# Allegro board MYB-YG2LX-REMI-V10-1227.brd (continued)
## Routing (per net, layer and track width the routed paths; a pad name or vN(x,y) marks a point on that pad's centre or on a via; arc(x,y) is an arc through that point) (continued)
RZ_DSI_DATA2_N: length 58.9
  TOP w0.13: v1(29.28,26.71) 29.11,26.54 28.78,26.54 R97.2 ; v1(60.21,52.94) 60.37,53.1 60.37,54.44 60.69,54.75 60.69,55.09 60.35,55.43 U26.69
  ART03 w0.109: v1(60.21,52.94) 60.37,52.77 60.37,52.56 60.26,52.45 59.76,52.45 59.63,52.58 59.63,52.76 59.49,52.91 59.31,52.91 59.16,53.05 59.16,53.23 59.02,53.37 58.84,53.37 58.7,53.51 58.7,53.69 58.56,53.83 58.38,53.83 58.11,54.1 56.54,54.1 56.13,54.51 50.75,54.51 50.36,54.89 45.56,54.89 44.82,54.15 43.47,54.15 42.76,53.44 41.19,53.44 40.71,52.96 40.71,48.47 32.41,40.16 32.41,38.51 31.09,37.19 31.09,27.31 30.84,27.07 30.67,27.07 30.52,26.92 30.52,26.75 30.32,26.54 30.14,26.54 30.01,26.67 29.82,26.67 29.69,26.54 29.44,26.54 v1(29.28,26.71)
RZ_DSI_DATA2_P: length 58.9
  TOP w0.13: R96.2 28.78,26.21 29.11,26.21 v1(29.28,26.05) ; U26.68 61.35,55.43 61.01,55.09 61.01,54.62 60.7,54.3 60.7,53.1 v1(60.87,52.94)
  ART03 w0.109: v1(29.28,26.05) 29.44,26.21 30.45,26.21 31.41,27.18 31.41,37.05 32.73,38.37 32.73,40.03 41.04,48.34 41.04,52.83 41.33,53.11 42.9,53.11 43.61,53.83 44.96,53.83 45.69,54.56 50.23,54.56 50.61,54.18 55.99,54.18 56.4,53.77 57.98,53.77 59.63,52.12 60.4,52.12 60.7,52.42 60.7,52.77 v1(60.87,52.94)
RZ_DSI_DATA3_N: length 57.7
  TOP w0.13: v1(29.28,28.49) 29.11,28.32 28.78,28.32 R99.2 ; U26.78 51.68,55.84 51.68,55.49 v1(51.52,55.32)
  ART03 w0.109: v1(51.52,55.32) 51.39,55.19 51.1,55.19 50.94,55.36 50.94,55.49 51.17,55.73 51.17,55.86 51.07,55.96 50.94,55.96 50.7,55.73 50.57,55.73 50.08,56.21 45.03,56.21 44.73,55.91 44.73,55.48 44.62,55.37 44.18,55.37 44.07,55.48 44.07,55.91 43.77,56.21 42.26,56.21 39.61,53.57 38.96,53.57 38.58,53.19 38.58,52.39 38.88,52.09 39.77,52.09 39.88,51.98 39.88,51.54 39.77,51.43 38.88,51.43 38.58,51.13 38.58,50.42 38.88,50.12 39.77,50.12 39.88,50.01 39.88,49.58 39.77,49.47 37.88,49.47 37.51,49.1 37.51,48.34 37.41,48.23 36.54,48.23 36.24,47.93 36.24,47.22 36.54,46.92 37.38,46.92 37.49,46.81 37.49,46.62 36.84,45.97 35.78,45.97 35.25,45.44 35.25,44.64 35.07,44.45 33.52,44.45 33.19,44.12 33.19,43.49 32.98,43.28 31.72,43.28 31.24,42.8 31.24,42.08 32.03,41.29 32.03,41.07 31.52,40.56 31.52,38.82 30.25,37.55 30.25,28.53 30.04,28.32 29.44,28.32 v1(29.28,28.49)
RZ_DSI_DATA3_P: length 57.8
  TOP w0.13: v1(29.28,27.83) 29.11,27.99 28.78,27.99 R98.2 ; v1(52.18,55.32) 52.01,55.49 52.01,55.84 U26.77
  ART03 w0.109: v1(29.28,27.83) 29.44,27.99 30.17,27.99 30.58,28.4 30.58,37.41 31.85,38.68 31.85,40.43 32.36,40.94 32.36,41.43 31.57,42.22 31.57,42.66 31.86,42.95 33.12,42.95 33.52,43.36 33.52,43.98 33.66,44.12 35.2,44.12 35.58,44.5 35.58,45.31 35.92,45.64 36.98,45.64 37.82,46.48 37.82,46.95 37.52,47.25 36.68,47.25 36.57,47.36 36.57,47.8 36.68,47.9 37.54,47.9 37.84,48.21 37.84,48.96 38.02,49.14 39.9,49.14 40.2,49.44 40.2,50.15 39.9,50.45 39.02,50.45 38.91,50.56 38.91,51 39.02,51.11 39.9,51.11 40.2,51.41 40.2,52.12 39.9,52.42 39.02,52.42 38.91,52.53 38.91,53.05 39.1,53.24 39.75,53.24 42.39,55.88 43.64,55.88 43.74,55.77 43.74,55.34 44.05,55.04 44.75,55.04 45.06,55.34 45.06,55.77 45.16,55.88 49.95,55.88 50.97,54.87 51.86,54.87 52.06,55.07 52.06,55.2 v1(52.18,55.32)
RZ_MD_BOOT0: length 20.3
  TOP w0.152: U26.156 78.36,11.17 78.36,10.82 79.52,9.65 88.79,9.65 90.95,7.49 90.95,3.61 91.59,2.97 SW1.8
RZ_MD_BOOT1: length 22.2
  TOP w0.152: v1(91.46,4.25) SW1.7 93.4,4.25 94.03,4.88 94.03,7.16 93.65,7.54 92.54,7.54 91.35,8.74 90.62,8.74 88.97,10.39 80.94,10.39 80.35,10.99 U26.158
  BOTTOM w0.152: R64.1 92.38,4.4 92.22,4.25 v1(91.46,4.25)
RZ_MD_BOOT2: length 18.2
  TOP w0.152: SW1.6 91.69,5.51 91.46,5.74 v1(91.46,6.3) 91.46,7.47 88.97,9.96 79.7,9.96 79.35,10.31 U26.157
  BOTTOM w0.152: v1(91.46,6.3) 91.49,6.32 R65.1
RZ_P1_0_USER_KEY: length 131.6
  TOP w0.152: v1(46.4,42.19) 46.81,41.78 46.81,37.52 46.47,37.18 U26.100 ; v1(112.95,5.69) 113.51,5.13 S2.4 S2.3
  ART03 w0.152: v1(104.03,6.76) 103.04,5.77 97.11,5.77 96.16,6.72 90.69,6.72 87.78,9.63 85.54,9.63 84.38,10.79 78.53,10.79 78.13,10.39 67.79,10.39 66.8,11.38 57.3,11.38 56.82,10.9 49.26,10.9 44.75,15.41 44.75,18.2 44.11,18.85 41.36,18.85 37.41,22.8 37.41,27.76 37,28.17 37,38.66 41.47,43.13 45.46,43.13 v1(46.4,42.19)
  BOTTOM w0.152: C164.1 116.71,3.65 116.52,3.84 D38.2 115.23,3.85 R247.2 113.76,4.88 v1(112.95,5.69) 112.43,5.17 110.27,5.17 109.88,5.56 109.88,6.58 109.17,7.29 104.57,7.29 v1(104.03,6.76)
RZ_P1_1: length 3.6
  TOP w0.152: U26.L57 80.26,14.63 81.07,15.44 v1(81.15,15.44)
  BOTTOM w0.152: U9.9 81.94,15.34 R43.2 81.68,15.42 81.17,15.42 v1(81.15,15.44)
RZ_P4_1: length 36.1
  TOP w0.152: J13.13 v1(55.34,63.57) ; U26.L16 84.1,52.73 v1(83.84,52.98)
  ART03 w0.152: v1(83.84,52.98) 83.84,53.62 81.2,56.26 72.87,56.26 70.32,58.81 69.22,58.81 64.47,63.57 v1(55.34,63.57)
RZ_P16_1_1V8: length 23.7
  TOP w0.152: U7.9 22.31,32.12 22.75,31.67 v1(23.52,31.67) ; v1(26.45,17.66) R76.2 R80.1
  ART03 w0.152: v1(26.45,17.66) 25.07,19.05 25.07,27.03 25.98,27.94 25.98,31.11 24.46,32.64 23.95,32.64 23.52,32.21 v1(23.52,31.67)
RZ_P22_1_ETH0: length 97.6
  TOP w0.152: J13.7 47.72,63.54 49.07,64.9 49.07,68.35 v1(49.02,68.4) ; U26.L3 v1(85.72,19.71)
  ART03 w0.152: v1(85.72,19.71) 86.71,20.7 87.46,20.7 88.57,21.81 88.57,38.46 90.88,40.77 90.88,45.68 88.97,47.59 88.97,50.22 88.41,50.77 88.41,56.21 85.72,58.9 84.58,58.9 82.44,61.04 78.71,61.04 77.34,59.66 74.45,59.66 73.53,60.59 73.53,63.98 72.89,64.62 72.89,67.16 71.65,68.4 v1(49.02,68.4)
RZ_P23_0_ETH0: length 83.3
  TOP w0.152: J13.15 57.88,63.44 59,64.57 v1(59,67.34) ; U26.L4 v1(85.72,22.25)
  ART03 w0.152: v1(59,67.34) 59.66,68 71.47,68 72.44,67.03 72.44,64.47 73.17,63.73 73.17,60.27 74.09,59.36 77.64,59.36 78.84,60.55 82.32,60.55 84.35,58.52 85.67,58.52 88.08,56.11 88.08,50.44 88.46,50.06 88.46,47.5 89.89,46.08 89.89,40.23 88.26,38.61 88.26,23.34 87.6,22.68 86.15,22.68 v1(85.72,22.25)
RZ_P23_1_ETH0: length 62.7
  TOP w0.152: U26.L2 v1(85.75,17.17) ; J13.29 75.66,60.38 75.97,60.07 v1(77.14,60.07)
  ART03 w0.152: v1(77.14,60.07) 79.04,61.98 83.64,61.98 88.74,56.87 88.74,50.98 89.23,50.5 89.76,50.5 90.32,49.94 90.32,46.86 91.33,45.85 91.33,40.67 88.87,38.2 88.87,20.07 88.49,19.68 87.07,19.68 85.75,18.36 v1(85.75,17.17)
RZ_P27_0_ETH0: length 49
  TOP w0.152: v1(84.76,23.83) 84.63,23.95 U26.L5 ; J13.31 78.2,60.38 78.51,60.07 v1(79.12,60.07)
  ART03 w0.152: v1(84.76,23.83) 84.63,23.95 84.63,25.25 87.14,27.76 87.14,29.74 86.69,30.2 86.69,32.97 86.33,33.32 86.33,33.93 87.93,35.53 87.93,39.14 89.23,40.44 89.23,45.14 88.67,45.69 88.67,46.72 87.87,47.52 87.87,49.95 87.7,50.11 87.7,55.96 86.31,57.35 84.96,57.35 82.24,60.07 v1(79.12,60.07)
RZ_P32_0_ETH1: length 55.4
  TOP w0.152: v1(84.73,28.75) 84.63,28.85 U26.L7 ; J13.22 v1(65.5,65.02)
  ART03 w0.152: v1(84.73,28.75) 84.63,28.85 84.63,29.59 85.62,30.58 85.62,31.57 84.63,32.56 84.63,38.96 86.41,40.74 86.41,43.38 85.34,44.45 85.34,46.15 85.67,46.48 85.67,49.35 85.42,49.61 85.42,52.83 81.63,56.62 73.17,56.62 70.53,59.26 69.62,59.26 65.5,63.38 v1(65.5,65.02)
RZ_P32_1_ETH1: length 58.6
  TOP w0.152: U26.L10 v1(85.47,37.49) ; J13.12 v1(52.8,65.02)
  ART03 w0.152: v1(85.47,37.49) 85.47,39.27 86.86,40.67 86.86,45.01 86.1,45.77 86.1,49.58 85.77,49.91 85.77,53.01 81.2,57.58 73.05,57.58 68.17,62.46 68.17,63.75 66.21,65.71 53.49,65.71 v1(52.8,65.02)
RZ_P33_0_ETH1: length 60
  TOP w0.152: v1(69.59,67.56) 69.59,67.16 69.77,66.98 J13.26 ; v1(84.73,26.26) 84.63,26.37 U26.L6
  ART03 w0.152: v1(69.59,67.56) 70.35,66.8 70.35,65.18 72.49,63.04 72.49,59.97 73.83,58.62 81.61,58.62 83.82,56.41 85.09,56.41 86.79,54.71 86.79,54.2 86.15,53.57 86.15,50.27 86.58,49.83 86.58,46.71 88.24,45.06 88.24,41.15 87.7,40.61 87.27,40.61 86.61,39.95 86.61,39.01 85.9,38.3 85.9,37.06 85.01,36.17 85.01,32.79 86.13,31.67 86.13,30.3 85.37,29.54 85.37,26.97 84.73,26.34 v1(84.73,26.26)
RZ_P36_1_ETH1: length 59
  TOP w0.152: U26.L9 v1(85.47,34.95) ; v1(71.42,67.36) 71.42,67.77 73.05,69.39 77.75,69.39 78.2,68.94 J13.32
  ART03 w0.152: v1(71.42,67.36) 70.76,66.7 70.76,65.41 72.84,63.32 72.84,60.12 73.94,59.03 82.72,59.03 84.93,56.82 86.05,56.82 87.37,55.5 87.37,53.72 86.48,52.83 86.48,50.65 87,50.13 87,46.89 88.64,45.25 88.64,40.56 87.75,39.67 87.32,39.67 87.02,39.37 87.02,38.81 86.23,38.02 86.23,35.71 v1(85.47,34.95)
RZ_P39_0: length 50.2
  TOP w0.152: U26.129 51.35,10.54 51.2,10.39 49.99,10.39 49.01,9.41 47.22,9.41 46.96,9.68 46.96,9.93 46.76,10.13 46.02,10.13 v1(45.56,10.59) ; v1(27.4,32.82) 27.83,33.25 27.83,34.39 27.66,34.57 26.89,34.57 26.1,35.37 U7.17
  ART03 w0.152: v1(45.56,10.59) 45.36,10.59 44.29,9.53 41.35,9.53 38.93,11.94 35.71,11.94 32.25,15.39 29.79,15.39 28.57,16.61 28.57,18.19 28.11,18.64 27.37,18.64 26.95,19.07 26.95,22.83 27.17,23.06 27.17,29.36 27.33,29.51 27.33,31.01 27.63,31.32 27.63,32.59 v1(27.4,32.82)
RZ_P39_0_1V8: length 14.3
  TOP w0.152: R23.1 v1(14.47,44.16) ; R29.2 18.03,34.65 v1(18.28,34.65) 19.01,35.37 U7.4
  BOTTOM w0.152: v1(18.28,34.65) 18.28,37.29 16.68,38.89 16.68,40.13 15.92,40.89 15.92,42.7 v1(14.47,44.16)
RZ_P39_1: length 32.6
  TOP w0.152: U7.16 26.16,34.72 26.84,34.04 v1(27.35,34.04) ; U26.97 v1(46.36,40.18)
  BOTTOM w0.152: v1(27.35,34.04) 28.57,34.04 29.33,34.8 29.92,34.8 33.45,31.27 36.52,31.27 37.46,30.33 43.35,30.33 45.03,32 45.03,38.86 v1(46.36,40.18)
RZ_P39_1_1V8: length 20.7
  TOP w0.152: R30.2 17.76,33.34 v1(18.28,33.86) 19.14,34.72 U7.5 ; v1(13.59,46.66) 13.48,46.56 12.42,46.56 11.78,45.92 J2.6
  BOTTOM w0.152: v1(13.59,46.66) 13.59,46.48 13.81,46.25 13.81,43.43 14.47,42.77 14.47,38.79 15.24,38.02 15.82,38.02 17.81,36.03 17.81,34.33 v1(18.28,33.86)
RZ_P39_2: length 28.6
  TOP w0.152: v1(27.01,33.29) 26.23,34.07 U7.15 ; U26.102 v1(46.36,35.18)
  BOTTOM w0.152: v1(27.01,33.29) 28.81,33.29 29.1,32.99 30.12,32.99 33.8,29.31 44.19,29.31 45.84,30.96 45.84,34.67 v1(46.36,35.18)
RZ_P39_2_1V8: length 21.5
  TOP w0.152: J2.7 11.77,46.42 12.32,46.96 v1(13.08,46.96) ; R31.2 18.28,33.12 v1(18.28,33.12) 19.23,34.07 U7.6
  BOTTOM w0.152: v1(18.28,33.12) 17.24,34.16 17.24,36.17 15.72,37.69 15.08,37.69 14.17,38.61 14.17,42.49 13.45,43.22 13.45,45.86 13.08,46.23 v1(13.08,46.96)
RZ_P40_2: length 30.6
  TOP w0.152: J13.11 v1(52.8,63.57) ; U26.98 v1(46.36,39.18)
  ART04 w0.152: v1(52.8,63.57) 52.8,60.65 47.62,55.47 47.62,51.1 46.4,49.89 46.4,45.92 47.14,45.19 47.14,39.96 v1(46.36,39.18)
RZ_P42_2: length 126.9
  TOP w0.152: v1(15.57,37.24) 15.57,37.64 16.18,38.25 18.18,38.25 18.75,37.68 21.88,37.68 23.69,35.86 23.69,33.81 24.09,33.42 U7.14 ; U26.43 v1(86.35,54.47)
  ART03 w0.152: v1(86.35,54.47) 86.35,54.59 84.98,55.96 83.82,55.96 81.48,58.29 73.4,58.29 69.31,62.38 69.31,65.46 67.94,66.83 49.58,66.83 48.23,68.17 33.04,68.17 30.68,65.81 30.68,62.69 26.62,58.62 22.86,58.62 20.9,56.67 15.34,56.67 11.08,52.41 11.08,45.43 10.33,44.68 10.33,38.96 12.72,36.58 15.06,36.58 15.57,37.08 v1(15.57,37.24)
RZ_P42_2_1V8: length 23.6
  TOP w0.152: U7.7 22.21,33.42 v1(22.53,33.73) ; v1(27.01,18) 27.01,18 27.01,18.21 R81.1
  ART03 w0.152: v1(22.53,33.73) 23.08,33.17 25.29,33.17 26.74,31.72 26.74,31.2 26.34,30.79 26.34,27.71 25.47,26.85 25.47,19.53 v1(27.01,18)
RZ_P42_3: length 117.6
  TOP w0.152: R87.1 14.89,29.62 R84.2 14.89,29.66 15.46,30.23 15.46,32.82 15.95,33.3 15.95,33.71 15.52,34.14 15.52,34.72 14.7,35.53 14.45,35.53 v1(13,36.98) ; U26.44 v1(85.35,54.47)
  ART03 w0.152: v1(85.35,54.47) 84.82,54.47 81.38,57.91 73.28,57.91 68.96,62.23 68.96,65.23 68.09,66.09 49.7,66.09 48.05,67.74 33.22,67.74 31.01,65.53 31.01,62.59 26.72,58.29 23.14,58.29 21.08,56.24 15.52,56.24 11.48,52.2 11.48,45.16 10.64,44.32 10.64,39.34 v1(13,36.98)
RZ_P42_4: length 26.5
  TOP w0.152: J13.36 v1(83.28,68.95) ; U26.41 v1(90.6,53.18)
  ART03 w0.152: v1(90.6,53.18) 90.6,55.37 92.1,56.87 92.1,59.31 89.43,61.98 89.43,66.07 86.1,69.39 83.72,69.39 v1(83.28,68.95)
RZ_P43_0: length 46.7
  TOP w0.152: v1(46.36,38.18) 45.35,38.18 U26.99 ; R86.1 14.89,28.73 R83.2 15.79,28.72 17.37,30.3 17.37,30.81 17.6,31.04 21,31.04 21.56,31.6 22.22,31.6 22.86,30.96 25.95,30.96 26.54,30.38 27.22,30.38 28.11,31.27 28.11,32.99 v1(29.41,34.29)
  BOTTOM w0.152: v1(29.41,34.29) 32.89,30.81 36.22,30.81 37.28,29.74 43.66,29.74 45.41,31.5 45.41,37.24 v1(46.36,38.18)
RZ_P43_1: length 6.1
  TOP w0.152: U26.95 44.96,42.18 43.96,43.18 43.71,43.18 43.25,43.64 43.25,45.26 42.45,46.06 D42.2
RZ_P43_2: length 119.7
  TOP w0.152: v1(90.67,35.59) 90.8,35.59 91.21,35.99 U19.34 ; v1(44.24,44.04) 44.24,45.85 44.58,46.18 U26.91
  ART03 w0.152: v1(44.24,44.04) 46.07,44.04 47.34,42.77 47.34,40.59 46.42,39.67 40.48,39.67 38.43,37.62 38.43,32.21 38.73,31.9 38.73,29.46 39.6,28.59 39.6,26.13 39.3,25.82 39.3,22.63 40.06,21.87 43.46,21.87 43.74,21.59 44.51,21.59 45.99,20.11 45.99,18.22 46.12,18.08 46.4,18.08 46.67,17.82 46.67,17.47 46.17,16.97 46.17,15.81 48.85,13.13 61.21,13.13 61.69,13.61 66.8,13.61 68.31,12.1 76.28,12.1 78.36,14.17 85.7,14.17 86.15,13.72 88.99,13.72 91.61,16.34 91.61,20.39 92.6,21.39 92.6,22.76 92.32,23.04 92.32,28.67 92.55,28.91 92.55,30.76 91.13,32.18 91.13,35.13 v1(90.67,35.59)
  BOTTOM w0.152: v1(90.67,35.59) 91.33,35.59 R190.2
RZ_P43_3: length 124.6
  TOP w0.152: U26.94 v1(46.36,43.18)
  TOP w0.203: R191.2 R194.1 98.05,41.33 v1(97.91,41.33) 97.91,41.27 97.58,40.94 97.25,40.94 96.96,40.65 U19.13
  ART03 w0.152: v1(46.36,43.18) 46.81,42.73 46.81,41.06 46.47,40.72 40.94,40.72 37.92,37.69 37.92,29.01 38.45,28.47 38.45,24.77 38.99,24.22 38.99,22.51 41.05,20.45 41.95,20.45 42.09,20.59 44.51,20.59 45.18,19.91 45.18,19.23 45.67,18.75 45.67,15.86 48.7,12.83 61.51,12.83 62,13.31 66.67,13.31 68.19,11.79 76.84,11.79 78.81,13.77 84.98,13.77 86.48,12.27 90.09,12.27 90.42,12.6 90.42,14.2 92.53,16.31 92.53,20.32 94.08,21.87 94.08,29.57 96.77,32.26 96.77,40.18 v1(97.91,41.33)
RZ_P44_2: length 90.3
  TOP w0.152: U26.92 v1(46.36,45.18) ; v1(90.42,15.95) 90.47,15.9 90.75,15.9 91.21,16.36 U16.34
  ART03 w0.152: v1(90.42,15.95) 89.58,15.95 89.33,15.7 86.76,15.7 86.15,15.09 85.25,15.09 85.12,14.96 77.19,14.96 75.51,13.28 69.72,13.28 68.78,14.22 61.03,14.22 60.55,13.74 49.9,13.74 48.46,15.18 48.46,16.83 47.36,17.93 47.36,20.74 44.4,23.7 43.16,23.7 40.56,26.3 40.56,31.32 40.26,31.62 39.7,31.62 39.04,32.28 39.04,35.1 40.86,36.93 40.86,37.9 41.73,38.76 46.51,38.76 47.75,40 47.75,43.79 v1(46.36,45.18)
  BOTTOM w0.152: U16.34 91.35,15.95 v1(90.42,15.95)
RZ_P44_3: length 109.7
  TOP w0.152: U16.13 97.44,20.76 99.02,22.34 R157.1 R155.2 v1(100.77,22.34) ; U26.96 v1(46.36,41.18)
  ART03 w0.152: v1(100.77,22.34) 99.41,20.98 99.41,16.71 97.89,15.19 92.02,15.19 90.8,13.97 90.8,12.5 90.27,11.96 86.15,11.96 85.19,12.93 78.56,12.93 77.12,11.49 68.06,11.49 66.54,13 62.21,13 61.6,12.4 57.15,12.4 56.26,11.51 49.56,11.51 45.36,15.71 45.36,18.46 44.33,19.48 42.85,19.48 42.19,20.14 40.93,20.14 38.63,22.44 38.63,24.03 38.12,24.54 38.12,28.17 37.61,28.68 37.61,37.92 40.87,41.18 v1(46.36,41.18)
RZ_P48_2: length 40.9
  TOP w0.152: v1(15.52,33.53) 14.91,33.53 R85.2 14.86,33.48 R94.1 ; v1(43.66,43.94) 43.96,43.64 44.62,43.64 45.17,44.18 U26.93
  ART04 w0.152: v1(17.22,41.05) 16.94,40.77 16.94,39.29 15.97,38.33 15.97,36.45 15.52,35.99 v1(15.52,33.53)
  BOTTOM w0.152: v1(43.66,43.94) 43.38,44.22 37.61,44.22 33.73,40.34 31.19,40.34 30.12,41.4 28.85,41.4 28.11,40.67 17.6,40.67 v1(17.22,41.05)
RZ_RIIC0_SCL: length 86.7
  TOP w0.152: U26.104 v1(46.36,33.18) ; v1(29.41,35.28) 29.23,35.1 T3.1 27.76,36 R33.2 27.28,36.02 U7.18 24.18,36.02 21.64,38.56 15.95,38.56 15.41,38.02 R92.1
  ART03 w0.152: v1(71.07,13.72) 70.99,13.79 69.64,13.79 68.91,14.53 60.9,14.53 60.42,14.05 50.03,14.05 48.76,15.31 48.76,16.95 47.66,18.05 47.66,18.9 48.54,19.78 48.54,22.4 46.96,23.98 46.96,32.57 v1(46.36,33.18) 43.42,36.12 41.25,36.12 40.56,35.43 40.56,33.25 v1(40.18,32.87)
  BOTTOM w0.152: v1(40.18,32.87) 40.03,33.02 38.5,33.02 37.23,31.75 33.5,31.75 29.97,35.28 v1(29.41,35.28) ; R51.2 R44.2 71.29,13.56 71.14,13.72 v1(71.07,13.72)
RZ_RIIC0_SDA: length 89.9
  TOP w0.152: U26.103 v1(46.36,34.18) ; v1(29.46,35.86) 29.55,35.96 T1.1 28.62,37.31 28.32,37.01 27.33,37.01 26.89,37.45 R32.2 26.61,37.54 26.39,37.32 U7.20 23.82,37.32 22.4,38.73 22.4,39.83 21.59,40.64 14.88,40.64 13.69,39.45 R91.1
  ART03 w0.152: v1(40.15,33.55) 40.15,35.56 41.04,36.45 44.09,36.45 v1(46.36,34.18) 47.32,33.22 47.32,25.12 48.05,24.38 48.05,23.34 48.84,22.56 48.84,19.65 47.97,18.78 47.97,18.18 49.07,17.08 49.07,15.44 50.16,14.35 60.3,14.35 60.78,14.83 69.03,14.83 69.34,14.53 v1(71.04,14.53)
  BOTTOM w0.152: R50.2 R46.2 71.29,14.45 71.22,14.53 v1(71.04,14.53) ; v1(29.46,35.86) 29.89,35.86 33.55,32.21 37.16,32.21 38.3,33.35 39.95,33.35 v1(40.15,33.55)
RZ_RIIC1_SCL: length 110.2
  TOP w0.152: v1(36.95,26.01) 36.85,26.01 36.54,25.7 R118.1 ; v1(49.6,30.96) 45.57,30.96 U26.106 44.74,31.18 44.22,30.66 44.22,27.94 43.76,27.48 v1(43.76,26.62)
  ART04 w0.152: v1(71.95,61.01) 71.75,61.21 63.47,61.21 56.46,54.2 53.82,54.2 52.62,53.01 50.59,53.01 49.4,51.82 49.4,49.76 48.87,49.23 48.87,31.7 v1(49.6,30.96)
  BOTTOM w0.152: R251.1 72.46,61.52 v1(71.95,61.01) ; R111.1 R108.2 15.46,5.41 15.21,5.66 15.21,11.35 14.27,12.29 12.37,12.29 12.04,12.62 12.04,15.11 12.95,16.03 17.93,16.03 19.12,17.22 22.27,17.22 23.39,18.34 24.91,18.34 26.27,19.69 27.51,19.69 28.11,20.29 29.49,20.29 33.7,24.51 35.68,24.51 36.95,25.78 v1(36.95,26.01) 38.63,26.01 38.81,25.83 39.44,25.83 40.2,26.59 43.73,26.59 v1(43.76,26.62)
RZ_RIIC1_SDA: length 134.4
  TOP w0.152: v1(42.9,27.05) 42.9,27.08 43.86,28.04 43.86,31.17 44.88,32.18 U26.105 45.95,32.18 46.48,31.65 49.58,31.65 v1(49.63,31.6) ; R119.1 v1(39.2,26.3)
  ART04 w0.152: v1(72.01,60.27) 71.42,60.86 63.72,60.86 55.47,52.6 50.61,52.6 49.7,51.7 49.7,49.63 49.22,49.15 49.22,32 v1(49.63,31.6)
  BOTTOM w0.152: R107.2 R112.1 23.63,3.99 15.77,3.99 14.75,5 14.75,11.33 14.09,11.99 11.98,11.99 11.5,12.47 11.5,15.34 12.54,16.38 17.62,16.38 18.89,17.65 22.04,17.65 23.11,18.72 24.56,18.72 25.9,20.07 27.2,20.07 29.05,21.92 29.41,21.92 29.87,22.38 31.06,22.38 33.6,24.92 35.56,24.92 36.45,25.81 36.45,26.29 36.8,26.64 38.85,26.64 v1(39.2,26.3) 39.27,26.3 39.95,26.97 42.82,26.97 v1(42.9,27.05) ; R252.1 85.2,60.26 84.55,59.61 72.67,59.61 v1(72.01,60.27)
RZ_RIIC2_SCL: length 84
  TOP w0.152: v1(46.66,59.61) 46.11,59.61 45.18,60.55 J13.5 ; v1(70.86,15.42) 70.35,14.91 70.35,13.79 70.86,13.28 72.08,13.28 73.43,14.63 U26.L55
  ART03 w0.152: v1(70.86,15.42) 70.84,15.44 60.52,15.44 60.04,14.96 50.41,14.96 49.68,15.69 49.68,18.37 49.22,18.83 49.22,19.17 49.45,19.4 49.45,22.89 48.89,23.44 48.89,25.3 48.41,25.78 48.41,28.27 49.07,28.93 49.07,47.73 v1(49.63,48.29)
  BOTTOM w0.152: v1(46.66,59.61) 47.11,59.16 50.72,59.16 52.65,57.23 52.65,53.24 51.86,52.45 49.73,52.45 49.3,52.02 49.3,49.45 49.15,49.3 49.15,48.77 v1(49.63,48.29)
RZ_RIIC2_SDA: length 90.6
  TOP w0.152: J13.3 42.64,62.91 43.3,63.58 45.61,63.58 46.11,63.08 46.11,61.3 46.86,60.55 46.86,60.1 47.34,59.61 v1(47.77,59.61) ; U26.L56 76.2,15.44 v1(71.52,15.44)
  ART03 w0.152: v1(49.63,48.92) 48.66,47.96 48.66,29.08 47.95,28.37 47.95,25.2 48.48,24.66 48.48,23.34 49.15,22.68 49.15,19.52 48.92,19.29 48.92,18.7 49.37,18.25 49.37,15.56 50.28,14.66 60.17,14.66 60.65,15.14 69.34,15.14 69.49,14.99 71.07,14.99 v1(71.52,15.44)
  BOTTOM w0.152: v1(49.63,48.92) 49.65,48.95 49.65,51.79 49.96,52.1 52.07,52.1 53.03,53.06 53.03,57.38 50.8,59.61 v1(47.77,59.61)
RZ_RIIC3_SCL: length 79.7
  TOP w0.152: v1(74.34,60.88) 74.34,62.97 73.12,64.19 J13.28 ; v1(85.04,15.52) 84.52,15.52 83.93,14.92 83.93,12.54 84.35,12.12 U26.162
  ART03 w0.152: v1(74.34,60.88) 76.45,62.99 84.22,62.99 89.61,57.61 89.61,52.65 90.6,51.66 90.6,51.26 91.26,50.6 91.26,47.02 92.17,46.1 92.17,38.05 91.16,37.03 90.12,37.03 89.66,36.58 89.66,32.08 91.28,30.45 91.28,29.87 90.52,29.11 90.52,27.91 91.04,27.39 91.04,25.03 89.76,23.75 89.76,19.86 89,19.1 89,18.08 88.67,17.75 87.19,17.75 86.69,17.25 86.69,16.94 85.77,16.03 85.54,16.03 v1(85.04,15.52)
RZ_RIIC3_SDA: length 72.3
  TOP w0.152: v1(74.42,60.27) 74.16,60.02 73.81,60.02 73.12,60.71 J13.27 ; v1(85.01,16.13) 84.7,16.13 83.56,14.99 83.56,12.4 83.35,12.18 U26.161
  ART03 w0.152: v1(85.01,16.13) 85.49,16.61 85.87,16.61 86.29,17.03 86.29,18.25 86.81,18.77 88.08,18.77 89.23,19.91 89.23,38 91.79,40.56 91.79,45.97 90.83,46.94 90.83,50.29 90.12,51 90.12,51.51 89.12,52.5 89.12,57.35 83.89,62.59 76.73,62.59 v1(74.42,60.27)
RZ_RSPI0_CK: length 60.9
  TOP w0.152: v1(67.31,63.47) 68.04,62.74 J13.23 ; v1(49.45,23.52) 49.42,23.5 48.97,23.5 47.67,24.79 46.22,24.79 45.61,24.18 U26.113
  ART04 w0.152: v1(49.45,23.52) 48.51,24.46 48.51,49.33 49.07,49.89 49.07,52.11 51.16,54.2 52.35,54.2 53.03,54.89 53.03,57.81 58.7,63.47 v1(67.31,63.47)
RZ_RSPI0_MISO: length 73.4
  TOP w0.152: v1(38.45,47.55) 37.66,48.34 37.66,49.66 37.13,50.19 37.13,51.18 37.82,51.87 37.82,55.63 40.97,58.78 63.72,58.78 65.5,60.55 J13.21 ; U26.111 v1(44.34,26.18)
  BOTTOM w0.152: v1(38.45,47.55) 39.85,46.15 46.63,46.15 48.51,44.27 48.51,30.45 48.89,30.07 48.89,28.75 47.37,27.23 45.39,27.23 v1(44.34,26.18)
RZ_RSPI0_MOSI: length 74.4
  TOP w0.152: J13.19 62.96,59.61 62.53,59.18 40.81,59.18 37.49,55.85 37.49,51.99 36.78,51.28 36.78,49.99 37.33,49.43 37.33,48.08 38.27,47.14 38.65,47.14 v1(39.07,47.56) ; U26.112 v1(44.34,25.18)
  BOTTOM w0.152: v1(44.34,25.18) 46.06,26.9 47.65,26.9 49.22,28.47 49.22,30.18 48.87,30.53 48.87,44.42 45.36,47.93 39.44,47.93 v1(39.07,47.56)
RZ_RSPI0_SSL: length 64.7
  TOP w0.152: U26.114 v1(44.34,23.18) ; J13.24 v1(68.04,68.95)
  ART04 w0.152: v1(44.34,23.18) 45.26,24.1 45.26,28.04 45.79,28.57 45.79,54.64 52.27,61.11 52.27,63.62 57.6,68.95 v1(68.04,68.95)
RZ_SCIF0_RXD: length 63.6
  TOP w0.152: U26.123 44.69,14.18 v1(44.34,14.53)
  ART03 w0.152: v1(9.8,21.29) 10.21,20.88 10.21,16.19 13.14,13.26 15.49,13.26 17.09,11.66 23.86,11.66 24.87,12.67 31.77,12.67 36.31,8.14 45.7,8.14 46.94,9.37 46.94,11.13 46.38,11.68 46.38,12.5 v1(44.34,14.53)
  BOTTOM w0.152: R259.2 10.38,18.31 10.53,18.46 10.53,20.55 v1(9.8,21.29) 10.04,21.52 Q6.2 9.31,22.51 8.43,23.39 8.1,23.39 7.82,23.67 7.82,24.89 7.97,25.05 R257.2
RZ_SCIF0_TXD: length 70.3
  TOP w0.152: U26.122 v1(44.34,15.18)
  ART03 w0.152: v1(44.34,15.18) 44.52,15.18 47.8,11.9 47.8,9.65 45.94,7.79 36.23,7.79 31.65,12.37 25.17,12.37 24.15,11.35 16.68,11.35 15.08,12.95 9.75,12.95 9.19,13.51 v1(9.19,16.08) 9.19,23.01 9.9,23.72 v1(9.9,23.85)
  BOTTOM w0.152: v1(9.9,23.85) 10.13,24.08 10.13,25 R262.2 10.72,25.69 Q7.2 ; v1(9.19,16.08) 9.17,16.1 8.71,16.1 7.97,16.84 7.97,18.1 R261.2
RZ_SCIF1_CTS: length 70.1
  TOP w0.152: v1(44.32,18.06) 44.45,18.06 44.57,18.18 U26.119
  ART03 w0.152: v1(44.32,18.06) 43.58,17.32 38.58,17.32 34.29,21.62 31.92,21.62 30.76,20.45 29.71,20.45 29.57,20.31 29.11,20.31 28.87,20.55 28.87,28.93 29.94,30 29.94,31.11 29.63,31.42 29.52,31.42 28.93,32.01 28.93,35.08 27.94,36.07 23.75,36.07 22.22,37.59 20.49,37.59 19.6,38.48 19.6,39.97 18.63,40.94 18.5,40.94 18.26,41.18 18.26,44.53 19.05,45.31 21.13,45.31 23.01,47.19 26.16,47.19 28.14,49.17 28.14,51.33 28.47,51.66 30.58,51.66 30.68,51.77 v1(30.96,51.77)
  BOTTOM w0.152: v1(30.96,51.77) 30.78,51.77 R220.2
RZ_SCIF1_RTS: length 73.1
  TOP w0.152: U26.118 44.86,19.18 43.89,18.21 43.89,16.26 v1(44.29,15.85)
  ART03 w0.152: v1(44.29,15.85) 38.53,15.85 33.68,20.7 32.31,20.7 30.16,18.54 28.78,18.54 27.53,19.8 27.53,29.29 27.66,29.41 27.66,30.84 27.94,31.11 27.94,34.04 27.15,34.82 22.63,34.82 21.66,35.79 20.85,35.79 18.76,37.88 17.96,37.88 16.79,39.05 16.79,44.86 18.33,46.41 20.67,46.41 21.87,47.6 21.87,48.36 23.31,49.81 25.85,49.81 v1(27.89,51.84)
  BOTTOM w0.152: v1(27.89,51.84) 28.14,52.1 R221.2
RZ_SCIF1_RXD: length 65.6
  TOP w0.152: U26.120 44.43,17.18 v1(44.34,17.09)
  ART03 w0.152: v1(44.34,17.09) 44.27,17.02 38.32,17.02 34.03,21.31 32.06,21.31 29.95,19.2 29.27,19.2 28.98,19.49 28.98,19.94 28.57,20.35 28.57,29.23 29.21,29.88 29.21,30.65 28.6,31.27 28.6,34.98 27.89,35.69 23.34,35.69 21.89,37.13 20.52,37.13 19.25,38.4 19.25,39.89 18.5,40.64 18.36,40.64 17.93,41.07 17.93,44.83 18.79,45.69 21.03,45.69 24.35,49.02 27.35,49.02 v1(27.73,49.4)
  BOTTOM w0.152: R218.2 v1(27.73,49.4)
RZ_SCIF1_TXD: length 68.4
  TOP w0.152: U26.121 44.65,16.18 v1(44.34,16.48)
  ART03 w0.152: v1(27.73,50.3) 26.82,50.3 25.9,49.38 23.42,49.38 22.35,48.3 22.35,47.55 20.87,46.08 18.64,46.08 17.62,45.06 17.62,40.59 17.11,40.08 17.11,39.15 17.96,38.3 18.89,38.3 21.08,36.12 21.89,36.12 22.78,35.23 27.2,35.23 28.29,34.14 28.29,31.06 28.91,30.45 28.91,30.06 27.96,29.11 27.96,19.8 28.86,18.9 30.08,18.9 32.19,21.01 33.83,21.01 38.35,16.48 v1(44.34,16.48)
  BOTTOM w0.152: R219.2 v1(27.73,50.3)
RZ_SCIF2_CTS: length 89.6
  TOP w0.152: v1(38.55,54.18) 38.55,55.02 41.65,58.12 64.36,58.12 65.43,59.18 82.57,59.18 83.28,59.89 J13.35 ; U26.110 v1(44.42,27.18)
  BOTTOM w0.152: v1(44.42,27.18) 44.8,27.56 47.19,27.56 48.54,28.91 48.54,30 48.15,30.38 48.15,44.15 46.58,45.72 39.62,45.72 37.44,47.9 37.44,51 38.12,51.69 38.12,54.03 38.27,54.18 v1(38.55,54.18)
RZ_SCIF2_RXD: length 93.3
  TOP w0.152: v1(39.92,54.76) 42.57,57.4 64.64,57.4 65.76,58.52 85.87,58.52 87.3,59.94 87.3,62.61 88.36,63.67 J13.40 ; v1(46.4,30.25) 46.33,30.18 U26.107
  BOTTOM w0.152: v1(46.4,30.25) 46.4,32.49 46.96,33.05 46.96,43.36 45.28,45.03 39.32,45.03 36.78,47.57 36.78,51.28 37.49,51.99 37.49,54.48 37.99,54.99 39.7,54.99 v1(39.92,54.76)
RZ_SCIF2_TXD: length 87.1
  TOP w0.152: v1(46.5,29.46) 46.22,29.18 U26.108 ; v1(39.37,54.58) 39.37,54.97 42.19,57.78 64.56,57.78 65.63,58.85 85.26,58.85 85.82,59.41 J13.37
  BOTTOM w0.152: v1(39.37,54.58) 38.12,54.58 37.82,54.28 37.82,51.87 37.13,51.18 37.13,47.73 39.47,45.39 45.46,45.39 47.42,43.43 47.42,32.92 47,32.5 47,29.96 v1(46.5,29.46)
RZ_SCIF3_RXD: length 73.7
  TOP w0.152: U26.131 53.35,10.5 52.63,9.78 50.42,9.78 49.44,8.8 46.82,8.8 v1(45.94,9.68)
  ART03 w0.152: v1(8.78,32.79) 8.84,32.84 9.71,32.84 11.07,31.49 11.07,17.35 12.8,15.62 14.42,15.62 17.14,12.9 20.24,12.9 20.87,12.27 23.61,12.27 25.15,13.81 27.77,13.81 28.19,13.39 32.1,13.39 32.41,13.08 33.22,13.08 33.42,12.88 33.42,12.09 34.39,11.13 38.68,11.13 40.98,8.83 45.38,8.83 45.94,9.4 v1(45.94,9.68)
  BOTTOM w0.152: R263.2 13.13,33.65 R265.2 12.43,34.16 9.35,34.16 Q8.2 8.68,33.5 8.68,33.17 8.78,33.07 v1(8.78,32.79)
RZ_SCIF3_TXD: length 79.4
  TOP w0.152: U26.130 52.35,10.44 51.99,10.09 50.21,10.09 49.24,9.11 47.1,9.11 v1(46.53,9.68)
  ART03 w0.152: v1(8.61,34.44) 8.38,34.21 8.38,31.29 v1(9.09,30.58) 10.71,28.96 10.71,17.07 12.57,15.21 14.27,15.21 16.89,12.6 19.76,12.6 20.39,11.96 23.73,11.96 25.27,13.5 27.56,13.5 28.01,13.06 31.98,13.06 34.26,10.77 38.4,10.77 40.69,8.48 45.61,8.48 46.53,9.4 v1(46.53,9.68)
  BOTTOM w0.152: R268.2 12.1,37.63 Q9.2 7.84,36.72 7.84,34.72 8.12,34.44 v1(8.61,34.44) ; v1(9.09,30.58) 9.67,31.17 12.88,31.17 13.03,31.32 R267.2
RZ_SCIF4_RXD: length 63
  TOP w0.152: v1(47.47,16.66) 48.15,15.98 48.15,13.67 49.35,12.47 U26.127 ; v1(51.02,64.9) 50.25,65.68 J13.10
  ART04 w0.152: v1(51.02,64.9) 50.99,64.9 49.7,63.61 49.7,59.28 45.49,55.07 45.49,29.01 44.88,28.4 44.88,24.66 43.94,23.72 43.94,20.01 44.19,19.76 47.06,19.76 47.47,19.35 v1(47.47,16.66)
RZ_SCIF4_TXD: length 78.8
  TOP w0.152: J13.8 v1(47.71,65.02) ; v1(47.39,9.82) 48.99,9.82 U26.128
  ART04 w0.152: v1(47.39,9.82) 47.39,10.59 46.96,11.02 45.36,11.02 44.67,11.71 43.33,11.71 35.91,19.13 35.91,24.74 36.27,25.1 36.27,26.21 35.86,26.62 35.86,34.42 36.19,34.75 36.19,36.4 31.62,40.97 31.62,45.75 32.05,46.18 32.05,49.25 32.46,49.66 32.46,51.74 34.03,53.31 34.03,55.91 34.64,56.52 38.4,56.52 41.63,59.74 42.11,59.74 47.38,65.02 v1(47.71,65.02)
RZ_SD1_CD_N: length 118.6
  TOP w0.152: U26.3 87.46,15.18 v1(87.4,15.24)
  ART04 w0.152: v1(87.4,15.24) 86.56,15.24 85.21,13.89 80.69,13.89 80.16,14.43 77.22,14.43 75.15,12.37 68.91,12.37 67.69,13.59 46.25,13.59 44.85,14.99 44.85,17.27 44.6,17.53 41.7,17.53 40.64,18.59 40.64,22.66 40.2,23.09 40.2,24.1 39.99,24.32 39.99,30.54 39.67,30.86 39.67,31.83 38.78,32.72 38.78,37.26 37.18,38.86 37.18,44.53 v1(36.6,45.11)
  BOTTOM w0.152: v1(36.6,45.11) 36.6,44.53 34.13,42.06 30.53,42.06 30.25,41.78 19.96,41.78 19.06,42.68 18.75,42.68 11.98,49.45 T13.1 12.01,52.07 R74.2 12,53.33 D24.2 12,55 12.82,55.83 J5.9
RZ_SD1_CLK: length 114.3
  TOP w0.152: v1(36.24,50.16) 35.68,49.61 U24.7 ; U26.2 88.28,14.25 87.02,14.25 v1(86.81,14.45)
  ART04 w0.152: v1(86.81,14.45) 86.79,14.45 85.62,13.28 84.4,13.28 84.02,12.9 80.79,12.9 80.01,13.69 77.79,13.69 75.83,11.73 68.17,11.73 67.89,12.01 66.38,12.01 66.23,12.17 66.23,12.55 66.08,12.7 65.77,12.7 65.62,12.55 65.62,12.17 65.47,12.01 61.7,12.01 61.55,12.17 61.55,12.75 61.4,12.9 61.09,12.9 60.94,12.75 60.94,12.17 60.79,12.01 60.48,12.01 60.33,12.17 60.33,12.75 60.18,12.9 59.87,12.9 59.72,12.75 59.72,12.17 59.57,12.01 59.26,12.01 59.11,12.17 59.11,12.75 58.96,12.9 58.65,12.9 58.5,12.75 58.5,12.17 58.35,12.01 58.04,12.01 57.89,12.17 57.89,12.75 57.74,12.9 57.43,12.9 57.28,12.75 57.28,12.17 57.13,12.01 56.49,12.01 55.67,12.83 45.84,12.83 44.88,13.79 43.85,13.79 43.38,14.26 43.38,16.54 43.17,16.74 42.79,16.74 42.64,16.59 42.64,15.62 42.48,15.47 42.18,15.47 42.03,15.62 42.03,16.59 41.87,16.74 40.9,16.74 39.44,18.2 39.44,21.82 38.96,22.3 38.96,25.32 38.45,25.83 38.45,26.97 38.6,27.13 39.14,27.13 39.29,27.28 39.29,27.58 39.14,27.73 38.6,27.73 38.45,27.89 38.45,28.19 38.6,28.34 39.14,28.34 39.29,28.5 39.29,28.8 39.14,28.95 38.6,28.95 38.45,29.11 38.45,29.41 38.6,29.56 39.14,29.56 39.29,29.72 39.29,30.02 39.14,30.17 38.6,30.17 38.45,30.33 38.45,30.53 38.73,30.81 38.73,31.52 37.79,32.46 37.79,36.91 35.56,39.14 35.56,39.4 35.71,39.55 36.32,39.55 36.47,39.7 36.47,40.01 36.32,40.16 35.71,40.16 35.56,40.31 35.56,40.61 35.71,40.77 36.32,40.77 36.47,40.92 36.47,41.22 36.32,41.38 35.71,41.38 35.56,41.53 35.56,41.83 35.71,41.99 36.32,41.99 36.47,42.14 36.47,42.44 36.32,42.6 35.71,42.6 35.56,42.75 35.56,43.05 35.71,43.21 36.32,43.21 36.47,43.36 36.47,43.66 36.32,43.82 35.71,43.82 35.56,43.97 35.56,46.58 35.71,46.74 36.47,46.74 36.62,46.89 36.62,47.29 36.45,47.47 34.89,47.47 34.72,47.65 34.72,49.81 35.07,50.16 v1(36.24,50.16)
RZ_SD1_CMD: length 114.4
  TOP w0.152: U26.6 v1(87.36,18.18) ; v1(36.95,53.57) 36.47,53.09 36.14,53.09 34.61,51.56 U24.4
  ART04 w0.152: v1(36.95,53.57) 37.05,53.47 42.06,53.47 42.72,52.81 42.72,50.77 41.98,50.04 41.66,50.04 41.36,49.74 41.36,46.8 41.56,46.59 42.25,46.59 42.41,46.74 42.41,48.67 42.56,48.82 42.86,48.82 43.02,48.67 43.02,46.77 43.19,46.59 43.47,46.59 43.63,46.74 43.63,48.67 43.78,48.82 44.08,48.82 44.24,48.67 44.24,46.13 44.08,45.98 41.51,45.98 41.36,45.83 41.36,45.58 41.51,45.42 44.49,45.42 44.75,45.16 44.75,29.67 43.42,28.33 43.42,26.96 42.8,26.34 42.8,20.12 43.51,19.41 46.48,19.41 46.81,19.08 46.81,16.89 46.43,16.51 46.43,15.55 47.2,14.78 65.12,14.78 65.32,14.99 72.51,14.99 73,15.47 80.55,15.47 81.01,15.01 83.54,15.01 84.04,15.52 84.04,16.64 85.59,18.18 v1(87.36,18.18)
RZ_SD1_D0: length 114.5
  TOP w0.152: U26.4 v1(87.36,16.18)
  ART04 w0.152: v1(36.01,48.87) 37.51,48.87 37.66,48.72 37.66,47.17 37.82,47.02 39.47,47.02 39.62,46.87 39.62,46.56 39.47,46.41 37.82,46.41 37.66,46.26 37.66,38.99 38.15,38.51 40.61,38.51 40.76,38.35 40.76,36.61 40.61,36.46 39.44,36.46 39.29,36.3 39.29,36 39.44,35.85 39.9,35.85 40.05,35.69 40.05,34.39 40.59,33.86 40.59,32.06 40.74,31.91 41.14,31.91 41.32,32.09 41.32,33.45 41.45,33.58 41.91,33.58 42.13,33.35 42.13,31.46 41.98,31.3 40.66,31.3 40.51,31.15 40.51,30.85 40.66,30.69 41.98,30.69 42.13,30.54 42.13,30.24 41.98,30.08 40.66,30.08 40.51,29.93 40.51,29.63 40.66,29.47 41.98,29.47 42.13,29.32 42.13,29.02 41.98,28.86 40.66,28.86 40.51,28.71 40.51,27.24 40.66,27.09 40.89,27.09 41.04,26.93 41.04,26.63 40.89,26.48 40.66,26.48 40.51,26.33 40.51,25.62 40.66,25.47 41.65,25.47 41.8,25.31 41.8,25.01 41.65,24.86 40.76,24.86 40.61,24.7 40.61,23.57 40.76,23.42 41.83,23.42 41.98,23.27 41.98,22.96 41.83,22.81 41.19,22.81 41.04,22.66 41.04,22.35 41.19,22.2 41.83,22.2 41.98,22.05 41.98,21.75 41.83,21.59 41.19,21.59 41.04,21.44 41.04,19.08 41.55,18.57 44.6,18.57 45.23,17.93 45.23,15.37 46.58,14.02 68.78,14.02 69.52,13.28 75.49,13.28 76.98,14.78 80.37,14.78 80.9,14.25 84.37,14.25 85.44,15.32 85.44,15.72 85.9,16.18 v1(87.36,16.18)
  BOTTOM w0.152: v1(36.01,48.87) 36.01,49.2 34.31,50.91 U23.4
RZ_SD1_D1: length 114.4
  TOP w0.152: U26.1 v1(87.36,13.18)
  ART04 w0.152: v1(87.36,13.18) 86.1,11.91 80.92,11.91 79.8,13.03 78.2,13.03 76.22,11.05 67.59,11.05 67.28,11.35 57.15,11.35 57.02,11.23 54.18,11.23 54.03,11.38 54.03,11.79 53.88,11.94 53.31,11.94 53.16,11.79 53.16,10.9 53.01,10.74 52.37,10.74 52.22,10.9 52.22,11.71 52.07,11.86 51.59,11.86 51.44,11.71 51.44,10.85 51.28,10.69 50.98,10.69 50.83,10.85 50.83,11.53 50.68,11.68 50.4,11.68 50.22,11.51 50.22,10.85 50.07,10.69 49.76,10.69 49.61,10.85 49.61,11.53 49.46,11.68 49.18,11.68 49,11.51 49,10.85 48.85,10.69 48.54,10.69 48.39,10.85 48.39,11.66 48.24,11.81 45.69,11.81 45,12.5 43.84,12.5 38.73,17.61 38.73,21.34 37.69,22.38 37.69,29.76 37.54,29.92 37.41,29.92 37.26,30.07 37.26,30.37 37.41,30.52 37.54,30.52 37.69,30.68 37.69,31.22 36.95,31.95 36.95,36.63 34.92,38.66 34.92,39.51 34.77,39.67 34.26,39.67 34.11,39.82 34.11,40.12 34.26,40.28 34.77,40.28 34.92,40.43 34.92,40.8 34.77,40.95 33.4,40.95 33.24,41.11 33.24,41.41 33.4,41.56 34.77,41.56 34.92,41.72 34.92,42.02 34.77,42.17 33.02,42.17 32.86,42.33 32.86,42.63 33.02,42.78 34.77,42.78 34.92,42.94 34.92,44.78 34.77,44.93 34.21,44.93 34.11,44.83 34.11,44.35 33.96,44.2 33.6,44.2 33.45,44.35 33.45,46.46 34.03,47.04 34.03,50.85 34.69,51.51 36.04,51.51 36.5,51.97 v1(36.5,52.32)
  BOTTOM w0.152: U23.7 33.42,52.86 35.89,52.86 36.42,52.32 v1(36.5,52.32)
RZ_SD1_D2: length 114.3
  TOP w0.152: U26.7 87.47,19.18 v1(87.37,19.28)
  ART04 w0.152: v1(42.07,52.72) 41.68,53.11 36.57,53.11 36.06,52.6 35,52.6 33.55,51.16 33.55,47.32 32.71,46.48 32.71,43.41 32.3,43 32.3,40.77 36.5,36.58 36.5,29.41 37.36,28.55 37.36,23.83 36.37,22.83 36.37,19.32 43.57,12.12 44.83,12.12 45.5,11.44 47.23,11.44 48.36,10.31 53.87,10.31 54.38,10.82 57.1,10.82 57.22,10.95 67.26,10.95 67.51,10.69 76.35,10.69 78.36,12.7 79.65,12.7 80.87,11.48 87.36,11.48 88.83,12.96 88.83,18.44 87.99,19.28 v1(87.37,19.28)
  BOTTOM w0.152: U23.9 39.22,53.51 40.53,53.51 40.85,53.19 41.6,53.19 v1(42.07,52.72)
RZ_SD1_D3: length 114.2
  TOP w0.152: U26.5 v1(87.36,17.18)
  ART04 w0.152: v1(42.31,51.18) 41.91,51.59 41.36,51.59 40.69,50.91 39.26,50.91 39.11,50.76 39.11,50.46 39.26,50.3 40.69,50.3 40.84,50.15 40.84,49.85 40.69,49.69 39.26,49.69 39.11,49.54 39.11,49.24 39.26,49.08 40.69,49.08 40.84,48.93 40.84,48.63 40.69,48.47 39.62,48.47 39.47,48.32 39.47,48.02 39.62,47.86 40.69,47.86 40.84,47.71 40.84,45.44 40.61,45.21 38.27,45.21 38.12,45.06 38.12,39.12 38.4,38.84 41.19,38.84 41.4,38.63 41.4,36.28 41.55,36.13 43.81,36.13 43.96,35.97 43.96,34.03 43.81,33.88 42.95,33.88 42.8,33.73 42.8,33.43 42.95,33.27 43.89,33.27 44.04,33.12 44.04,32.54 43.89,32.38 42.82,32.38 42.67,32.23 42.67,31.79 42.82,31.64 43.94,31.64 44.09,31.48 44.09,31.18 43.94,31.03 42.82,31.03 42.67,30.87 42.67,30.57 42.82,30.42 43.94,30.42 44.09,30.26 44.09,29.96 43.94,29.81 42.82,29.81 42.67,29.66 42.67,28.5 42.39,28.22 42.03,28.22 41.83,28.02 41.83,26.52 42.34,26.01 42.34,19.84 43.18,19 45.16,19 45.74,18.42 45.74,15.54 46.91,14.38 69.29,14.38 69.54,14.12 73.48,14.12 73.63,14.27 75.89,14.27 76.74,15.12 80.46,15.12 81.01,14.58 83.61,14.58 84.48,15.44 84.48,16.28 84.93,16.73 86.92,16.73 v1(87.36,17.18)
  BOTTOM w0.152: U23.12 40.33,51.56 40.56,51.79 41.7,51.79 v1(42.31,51.18)
RZ_SD1_WP_N: length 70
  TOP w0.152: J13.38 v1(85.82,68.95) ; U26.163 85.35,11.97 85.85,12.47 v1(85.85,15.54)
  ART03 w0.152: v1(85.85,15.54) 86.99,16.69 89.18,16.69 90.04,17.55 90.04,18.14 90.6,18.69 90.83,18.69 90.98,18.85 90.98,23.57 91.64,24.23 91.64,28.98 92.25,29.59 92.25,30.56 89.96,32.84 89.96,36.4 90.19,36.63 91.39,36.63 92.53,37.77 92.53,46.3 92.19,46.65 92.19,47.28 92.78,47.88 92.78,49.68 91.08,51.38 91.08,52.02 90.12,52.98 90.12,57.71 88.97,58.85 88.97,65.79 v1(85.82,68.95)
RZ_SSI0_BCK: length 40.6
  TOP w0.152: v1(58.77,10.49) 58.35,10.91 U26.136 ; R121.1 32.97,21.46 31.92,20.42 v1(31.92,19.33)
  ART03 w0.152: v1(31.92,19.33) 32.43,19.84 33.07,19.84 33.75,19.15 33.75,15.67 35.87,13.55 41.87,13.55 44.07,11.35 44.07,10.9 43.43,10.26 v1(43.1,10.26)
  ART04 w0.152: v1(58.77,10.49) 58.77,10.21 58.29,9.73 57.45,9.73 56.36,8.64 44.73,8.64 v1(43.1,10.26)
RZ_SSI0_RCK: length 33.8
  TOP w0.152: U26.135 57.35,10.24 56.35,9.24 v1(56.03,9.24) ; v1(32.53,19.35) 32.86,19.68 R122.1
  ART03 w0.152: v1(32.53,19.35) 32.81,19.35 33.35,18.82 33.35,15.57 35.71,13.21 38.88,13.21 40.05,12.04 42.69,12.04 v1(43.61,11.13)
  ART04 w0.152: v1(56.03,9.24) 55.86,9.07 45.07,9.07 44.67,9.46 44.67,10.34 43.89,11.13 v1(43.61,11.13)
RZ_SSI0_RXD: length 36.8
  TOP w0.152: U26.137 59.35,9.16 59.03,8.84 57.27,8.84 57.07,8.64 v1(57.07,8.59) ; R126.1 v1(32.48,18.8)
  ART03 w0.152: v1(42.67,11.25) 40.2,11.25 38.63,12.83 35.66,12.83 32.91,15.57 32.91,18.36 v1(32.48,18.8)
  ART04 w0.152: v1(42.67,11.25) 42.67,10.11 44.62,8.15 56.64,8.15 v1(57.07,8.59)
RZ_SSI0_TXD: length 36.1
  TOP w0.152: v1(44.17,10.11) 44.17,9.3 45.64,7.82 50.08,7.82 51.1,8.84 54.78,8.84 56.35,10.4 U26.134 ; v1(32.48,20.29) 32.76,20.57 R125.1
  ART03 w0.152: v1(44.17,10.11) 45,10.95 45,11.29 42.33,13.97 35.95,13.97 34.13,15.78 34.13,19.2 33.04,20.29 v1(32.48,20.29)
RZ_SSI1_BCK: length 26.4
  TOP w0.152: v1(45.08,9.63) 46.21,8.5 49.77,8.5 50.75,9.48 53.26,9.48 54.35,10.56 U26.132
  BOTTOM w0.152: U8.1 47.1,21.93 45.28,20.12 45.28,12.83 44.14,11.68 44.14,10.92 45.08,9.98 v1(45.08,9.63)
RZ_SSI1_BCK_1V8: length 39.9
  TOP w0.152: v1(23.26,19.25) 23.26,19.74 22.78,20.22 U11.60
  ART03 w0.152: v1(47.82,22.05) 47.11,22.05 45.03,24.13 44.27,24.13 41.73,26.67 41.73,27 v1(41.32,27.41)
  BOTTOM w0.152: v1(41.32,27.41) 39.95,27.41 39.67,27.13 36.55,27.13 36.01,27.66 32.03,27.66 30.25,29.44 29.38,29.44 28.01,28.07 28.01,21.51 26.95,20.45 25.6,20.45 24.41,19.25 v1(23.26,19.25) ; U8.4 48.6,22.54 48.1,22.05 v1(47.82,22.05)
RZ_SSI1_RCK: length 25.6
  TOP w0.152: v1(44.6,11.13) 44.6,9.42 45.83,8.19 49.9,8.19 50.87,9.17 54.61,9.17 55.35,9.91 U26.133
  BOTTOM w0.152: v1(44.6,11.13) 45.74,12.27 45.74,19.68 46.31,20.25 U8.8
RZ_SSI1_RCK_1V8: length 42
  TOP w0.152: v1(22.7,19.51) 22.38,19.83 U11.59
  ART03 w0.152: v1(42.41,27.41) 42.11,27.1 42.11,26.78 44.41,24.49 45.23,24.49 47.11,22.61 47.84,22.61 48.23,22.22 48.23,21.79 v1(47.85,21.41)
  BOTTOM w0.152: v1(47.85,21.41) 48.08,21.41 48.6,20.89 U8.5 ; v1(42.41,27.41) 41.86,27.97 32.25,27.97 30.45,29.77 28.93,29.77 27.56,28.4 27.56,21.62 26.77,20.83 25.29,20.83 24.2,19.74 22.93,19.74 v1(22.7,19.51)
RZ_SSI1_RXD: length 102.3
  TOP w0.152: v1(44.37,13.06) 44.49,13.18 U26.124 ; v1(38.91,48.23) 38.27,48.23 37.99,48.51 37.99,49.83 37.44,50.39 37.44,51 38.12,51.69 38.12,55.3 41.27,58.45 64.05,58.45 65.15,59.54 80.49,59.54 80.74,59.78 J13.33
  BOTTOM w0.152: v1(38.91,48.23) 38.96,48.29 45.51,48.29 49.2,44.6 49.2,30.71 49.58,30.33 49.58,28.24 47.88,26.54 46.17,26.54 45.31,25.68 45.31,22.17 44.8,21.67 44.8,13.64 44.37,13.21 v1(44.37,13.06)
RZ_SSI1_TXD: length 44.6
  TOP w0.152: v1(26.92,30.78) 27.68,31.55 27.68,32.08 27.38,32.38 26.77,32.38 26.39,32.77 U7.13 ; U26.126 48.35,10.49 48.2,10.34 47.06,10.34 46.83,10.57 v1(46.5,10.57)
  ART03 w0.152: v1(26.92,30.78) 26.77,30.63 26.77,27.18 26.36,26.77 26.36,19.22 27.43,18.15 27.43,16.89 27.76,16.56 27.99,16.56 29.51,15.04 32.15,15.04 35.68,11.51 38.78,11.51 41.11,9.18 45.24,9.18 45.49,9.42 45.49,9.83 46.22,10.57 v1(46.5,10.57)
RZ_SSI1_TXD_1V8: length 19.4
  TOP w0.152: v1(22.93,32.21) 22.37,32.77 U7.8 ; U11.58 21.98,20.3 22.04,20.24 22.04,19.56 v1(21.79,19.3)
  ART03 w0.152: v1(22.93,32.21) 23.11,32.03 23.11,31.47 23.72,30.86 23.72,29.08 22.96,28.32 22.96,20.47 v1(21.79,19.3)
RZ_USB0_DM: length 120.3
  TOP w0.155: J3.B7 79.85,4.76 79.92,4.7 79.92,4.32 v1(79.75,4.15) ; J3.A7 80.61,7.52 80.54,7.59 80.54,8.14 D7.2 80.56,8.71 80.56,9.05 v1(80.73,9.21) ; U26.51 78.35,55.42 78.69,55.09 78.69,54.58 78.53,54.42 78.14,54.42 v1(77.97,54.59)
  ART03 w0.137: v1(80.73,9.21) 80.51,9.44 80.51,9.77 80.9,10.16 81.09,10.16 81.24,10.01 81.5,10.01 81.65,10.16 81.91,10.16 82.07,10.01 82.32,10.01 82.48,10.16 82.73,10.16 82.89,10.01 83.14,10.01 83.3,10.16 83.68,10.16 85.08,8.76 87.4,8.76 91.41,4.75 103.96,4.75 105.2,5.99 105.2,9.48 104.49,10.19 104.49,53.39 102.79,55.09 99.74,55.09 98.14,56.69 93.41,56.69 v1(93.24,56.86)
  BOTTOM w0.155: v1(93.24,56.86) 93.07,56.69 91.87,56.69 88.95,53.77 84.58,53.77 83.93,54.42 78.14,54.42 v1(77.97,54.59) ; v1(80.73,9.21) 80.56,9.05 80.56,7.98 80.21,7.62 80.21,5.63 80.08,5.51 80.08,5.32 80.24,5.16 80.24,4.96 80.11,4.83 79.92,4.83 79.76,4.99 79.56,4.99 79.27,4.69 79.27,3.93 79.53,3.67 79.76,3.67 79.92,3.83 79.92,3.99 v1(79.75,4.15)
RZ_USB0_DP: length 120.3
  TOP w0.155: v1(80.41,4.15) 80.24,4.32 80.24,4.65 80.35,4.76 J3.B6 ; v1(77.97,53.93) 78.14,54.09 78.67,54.09 79.01,54.44 79.01,55.09 79.35,55.42 U26.50 ; v1(80.07,9.21) 80.23,9.05 80.23,8.75 D8.2 80.21,8.14 80.21,7.6 80.11,7.5 J3.A6
  ART03 w0.137: v1(93.24,56.2) 93.41,56.37 98.01,56.37 99.61,54.76 102.65,54.76 104.16,53.25 104.16,10.05 104.87,9.34 104.87,6.13 103.83,5.08 91.54,5.08 87.53,9.09 85.22,9.09 83.82,10.49 80.77,10.49 80.18,9.91 80.18,9.33 v1(80.07,9.21)
  BOTTOM w0.155: v1(93.24,56.2) 93.07,56.37 92,56.37 89.08,53.44 84.44,53.44 83.79,54.09 78.14,54.09 v1(77.97,53.93) ; v1(80.07,9.21) 80.24,9.05 80.24,8.11 79.88,7.75 79.88,5.77 78.94,4.83 78.94,3.79 79.39,3.34 79.9,3.34 80.24,3.69 80.24,3.99 v1(80.41,4.15)
RZ_USB0_OTG_ID: length 7.8
  TOP w0.152: U26.45 84.35,57.61 84.65,57.91 v1(85.57,57.91) 86.51,57.91 T5.1
  BOTTOM w0.152: v1(85.57,57.91) 85.47,57.81 R39.2 R48.1
RZ_USB0_VBUSIN: length 63.5
  TOP w0.152: U26.42 90.39,54.18 v1(91.46,53.11)
  ART03 w0.152: v1(91.46,53.11) 91.46,51.61 93.67,49.4 93.67,46.69 99.01,41.35 99.01,40.21 97.35,38.56 97.35,30.61 97.75,30.21 97.75,27.24 101.6,23.39 101.6,22.15 100.02,20.57 100.02,12.67 97.2,9.86 95.3,9.86 94.61,9.17 92.07,9.17 90.75,10.49 v1(89.72,10.49)
  BOTTOM w0.254: R35.1 v1(89.72,10.49)
RZ_USB1_DM: length 31.9
  TOP w0.155: U26.48 81.69,55.84 81.69,54.09 82.28,53.49 86.52,53.49 87.91,54.89 91.38,54.89 92.38,53.89 92.38,52.93 v1(92.21,52.77) ; v1(101.74,52.36) 101.58,52.53 101.28,52.53 D15.2 100.69,52.53 100.3,52.53 99.73,53.09 99.43,53.09 U10.1
  ART03 w0.137: v1(92.21,52.77) 92.38,52.6 92.38,51.73 94.35,49.76 99.9,49.76 100.55,50.41 100.55,52.19 100.89,52.53 101.58,52.53 v1(101.74,52.36)
RZ_USB1_DP: length 31.8
  TOP w0.155: v1(101.74,53.02) 101.58,52.86 101.28,52.86 D16.2 100.69,52.86 100.43,52.86 99.87,53.42 99.43,53.42 U10.2 ; U26.47 82.01,55.84 82.01,54.23 82.42,53.82 82.69,53.82 82.9,54.03 83.16,54.03 83.36,53.82 83.62,53.82 83.83,54.03 84.09,54.03 84.29,53.82 84.55,53.82 84.76,54.03 85.02,54.03 85.22,53.82 86.38,53.82 87.78,55.22 91.51,55.22 92.71,54.03 92.71,52.93 v1(92.87,52.77)
  ART03 w0.137: v1(101.74,53.02) 101.58,52.86 100.76,52.86 100.22,52.32 100.22,50.55 99.76,50.09 94.49,50.09 92.7,51.87 92.7,52.6 v1(92.87,52.77)
SD1_CLK: length 36.9
  TOP w0.152: U24.5 32.64,50.91 32,50.27 32,45.95 v1(31.01,44.96)
  BOTTOM w0.152: v1(31.01,44.96) 31.01,44.68 30.45,44.12 29.31,44.12 28.6,43.41 25.24,43.41 24.15,44.5 23.26,44.5 23.11,44.65 23.11,45.03 22.96,45.19 22.65,45.19 22.5,45.03 22.5,44.65 22.35,44.5 22.04,44.5 21.85,44.69 21.85,45.38 21.7,45.54 21.4,45.54 21.24,45.38 21.24,44.65 21.09,44.5 20.83,44.5 20.63,44.69 20.63,45.38 20.48,45.54 20.18,45.54 20.02,45.38 20.02,44.65 19.87,44.5 19.66,44.5 19.5,44.65 19.5,45.6 19.35,45.75 18.79,45.75 18.64,45.9 18.64,46.2 18.79,46.36 19.17,46.36 19.33,46.51 19.33,47.63 19.17,47.78 18.67,47.78 18.51,47.93 18.51,48.24 18.67,48.39 19,48.39 19.15,48.54 19.15,48.9 19,49.05 18.61,49.05 18.46,49.21 18.46,49.51 18.61,49.66 19.35,49.66 19.5,49.82 19.5,50.12 19.35,50.27 18.61,50.27 18.46,50.43 T11.1 18.48,51.23 R75.1
SD1_CMD: length 40.7
  TOP w0.152: U24.2 33.42,52.86 34.82,52.86 v1(35.48,53.52)
  BOTTOM w0.152: J5.3 20.35,55.14 20.7,54.79 D20.2 20.71,54.24 R70.2 20.54,53.24 T10.1 21.56,52.22 21.71,52.37 21.71,52.92 21.98,53.19 22.63,53.19 22.91,53.47 22.91,54 23.03,54.13 25.6,54.13 25.75,53.98 25.75,53.62 25.9,53.47 26.21,53.47 26.36,53.62 26.36,53.98 26.51,54.13 27.19,54.13 27.32,54.25 27.32,54.61 27.17,54.76 26.69,54.76 26.56,54.89 26.56,55.14 26.74,55.32 27.78,55.32 27.93,55.17 27.93,53.77 28.08,53.62 28.36,53.62 28.52,53.77 28.52,55.17 28.67,55.32 28.97,55.32 29.13,55.17 29.13,53.77 29.28,53.62 30.4,53.62 30.76,53.26 30.76,52.45 30.96,52.25 31.87,52.25 32.15,52.53 32.15,53.98 32.79,54.61 33.42,54.61 33.57,54.76 33.57,56.36 33.73,56.52 34.03,56.52 34.18,56.36 34.18,54.86 34.33,54.71 36.88,54.71 37.05,54.53 37.05,54.18 36.95,54.08 35.71,54.08 35.48,53.85 v1(35.48,53.52)
SD1_D0: length 42.1
  BOTTOM w0.152: J5.7 15.95,55.28 16.54,54.69 D22.2 16.54,53.31 R72.2 16.55,52.26 T12.1 16.46,50.05 16.64,49.86 17.55,49.86 17.71,49.71 17.71,49.41 17.55,49.25 17.11,49.25 16.96,49.1 16.96,48.8 17.11,48.65 17.55,48.65 17.71,48.49 17.71,48.19 17.55,48.04 17.11,48.04 16.96,47.88 16.96,47.58 17.11,47.43 17.55,47.43 17.71,47.27 17.71,46.97 17.55,46.82 17.11,46.82 16.96,46.66 16.96,46.34 17.13,46.16 17.69,46.16 17.84,46.01 17.84,45.17 19.4,43.61 19.88,43.61 20.11,43.38 20.11,42.95 20.34,42.72 20.76,42.72 20.91,42.88 20.91,43.41 21.06,43.56 21.37,43.56 21.52,43.41 21.52,42.88 21.67,42.72 22.5,42.72 22.65,42.88 22.65,43.31 22.81,43.46 23.11,43.46 23.26,43.31 23.26,42.88 23.42,42.72 29.56,42.72 29.99,43.15 31.97,43.15 32.91,44.09 32.91,46.35 34.59,48.03 34.59,49.3 34.29,49.61 U23.2
SD1_D1: length 42.2
  BOTTOM w0.152: U23.5 34.19,51.56 36.42,49.33 36.42,48.36 35.28,47.22 34.49,47.22 33.42,46.15 33.42,43.61 32.3,42.49 30.17,42.49 29.89,42.21 20.09,42.21 16.23,46.08 16.23,49.3 15.87,49.66 15.87,50.11 14.68,51.31 14.68,51.64 14.45,51.87 14.04,51.87 13.79,52.12 R73.2 13.8,53.33 D23.2 13.8,54.26 14.85,55.31 J5.8
SD1_D2: length 39.2
  TOP w0.152: v1(32.5,56.48) 34.5,54.48 36.17,54.48 v1(36.98,55.3)
  BOTTOM w0.152: v1(36.98,55.3) 40.1,55.3 40.74,54.66 40.74,53.82 41.07,53.49 41.91,53.49 42.49,52.91 42.49,52.55 42.14,52.21 39.22,52.21 U23.11 ; J5.1 22.55,58.9 22.75,59.11 23.52,59.11 23.67,58.95 23.67,58.17 23.82,58.01 24.13,58.01 24.28,58.17 24.28,58.95 24.43,59.11 24.74,59.11 24.89,58.95 24.89,58.17 25.04,58.01 25.35,58.01 25.5,58.17 25.5,58.95 25.65,59.11 25.96,59.11 26.11,58.95 26.11,58.17 26.26,58.01 26.57,58.01 26.72,58.17 26.72,58.95 26.87,59.11 27.48,59.11 27.66,58.93 27.66,58.57 27.81,58.42 28.85,58.42 28.95,58.32 28.95,57.96 29.03,57.89 29.46,57.89 29.57,58 29.57,58.83 29.72,58.98 30.1,58.98 30.25,58.83 30.25,56.65 30.4,56.49 D18.2 31.7,56.49 R68.2 v1(32.5,56.48)
SD1_D3: length 41.4
  ART03 w0.152: v1(31.1,53.57) 34.01,53.57 34.69,54.25 37.11,54.25 37.93,53.43 v1(37.93,50.76)
  BOTTOM w0.152: J5.2 21.45,53.85 21.6,53.7 21.99,53.7 22.14,53.85 22.14,54.46 22.3,54.61 23.35,54.61 23.5,54.76 23.5,57.28 23.65,57.43 23.95,57.43 24.11,57.28 24.11,54.76 24.26,54.61 24.56,54.61 24.72,54.76 24.72,57.28 24.87,57.43 25.17,57.43 25.33,57.28 25.33,54.76 25.48,54.61 25.83,54.61 25.98,54.76 25.98,55.6 26.13,55.75 28.7,55.75 28.83,55.88 28.83,57.15 28.98,57.3 29.43,57.3 29.59,57.15 29.59,54.33 29.74,54.18 D19.2 30.27,54.19 R69.2 v1(31.1,53.57) 31.54,53.12 T9.1 ; U23.14 38.44,50.26 v1(37.93,50.76)
SDIO_CLK: length 19.2
  TOP w0.152: U22.18 17.56,53 18.89,51.66 18.89,50.92 19.05,50.77 19.53,50.77 19.68,50.62 19.68,50.32 19.53,50.16 19.09,50.16 18.89,49.96 18.89,49.71 19.05,49.55 19.53,49.55 19.68,49.4 19.68,49.1 19.53,48.94 19.05,48.94 18.89,48.79 18.89,48.49 19.05,48.33 19.53,48.33 19.68,48.18 19.68,47.88 19.53,47.72 19.05,47.72 18.89,47.57 18.89,47.35 19.17,47.07 19.17,46.69 19.38,46.48 19.76,46.48 20.1,46.14 20.53,46.14 20.75,45.92 20.75,44.35 21.13,43.97 22.31,43.97 23.4,42.87 R235.1 R223.1
SDIO_CMD: length 17.9
  TOP w0.152: U22.17 17.83,53.9 20.87,50.85 20.87,48.7 21.03,48.55 21.33,48.55 21.48,48.4 21.48,48.09 21.33,47.94 21.03,47.94 20.87,47.79 20.87,47.12 21.81,46.18 22.35,46.18 22.5,46.02 22.5,44.65 23.16,43.99 24.06,43.99 25.18,42.87 R236.1 R224.1
SDIO_DATA0: length 12.2
  TOP w0.152: R225.1 R237.1 16.34,43.47 16.19,43.62 15.87,43.62 15.72,43.77 15.72,44.08 15.87,44.23 16.19,44.23 16.34,44.38 16.34,44.69 16.19,44.84 15.87,44.84 15.72,44.99 15.72,45.3 15.87,45.45 16.19,45.45 16.34,45.6 16.34,45.92 16.19,46.08 15.31,46.08 15.16,46.23 15.16,48.31 15.64,48.79 15.64,50.11 15.83,50.3 U22.21
SDIO_DATA1: length 8.5
  TOP w0.152: R238.1 R226.1 18.07,42.87 17.55,43.39 17.55,49.19 17.34,49.4 U22.22
SDIO_DATA2: length 11.1
  TOP w0.152: U22.20 17.09,51.2 17.88,50.41 17.88,44.45 18.87,43.46 19.31,43.46 R239.1 R227.1
SDIO_DATA3: length 13.3
  TOP w0.152: R228.1 R240.1 21.63,42.87 21.17,43.32 20.07,43.32 18.94,44.46 18.94,45.83 18.21,46.56 18.21,51.25 17.36,52.1 U22.19
TX0_DN: length 44.5
  TOP w0.13: v1(21.71,30.56) 21.55,30.39 21.55,29.36 21.58,29.33 U11.24 ; v1(20.82,15.06) 20.98,14.9 20.98,14.48 20.63,14.13 20.63,13.77 U13.C2
  ART03 w0.109: v1(21.71,30.56) 21.55,30.73 21.55,31.15 21.08,31.62 21.08,33.07 20.65,33.5 19.41,33.5 19.12,33.79 19.12,34.92 18.59,35.46 16.14,35.46 14.54,33.86 13.59,33.86 12.85,33.12 12.85,29.03 13.84,28.03 13.84,27.34 13.15,26.65 13.15,21.56 13.64,21.07 13.64,20.56 13.15,20.07 13.15,18.92 13.48,18.59 14.2,18.59 14.55,18.94 14.55,19.5 14.66,19.61 15.05,19.61 15.16,19.5 15.16,18.76 15.57,18.36 15.57,17.7 15.94,17.33 19.6,17.33 20.98,15.94 20.98,15.22 v1(20.82,15.06)
TX0_DN_OUT: length 2.8
  TOP w0.13: J7.9 20.63,11.63 20.93,11.93 20.93,12.16 20.62,12.47 20.62,12.9 U13.A2
TX0_DP: length 44.4
  TOP w0.13: U11.25 21.18,29.33 21.22,29.36 21.22,30.39 v1(21.05,30.56) ; v1(21.48,15.06) 21.3,14.89 21.3,14.34 20.96,13.99 20.96,13.77 U13.C1
  ART03 w0.109: v1(21.48,15.06) 21.31,15.22 21.31,15.37 21.41,15.47 21.85,15.47 21.94,15.57 21.94,15.7 21.85,15.8 21.41,15.8 21.31,15.89 21.31,16.07 19.73,17.65 16.08,17.65 15.9,17.84 15.9,18.49 15.49,18.9 15.49,19.64 15.19,19.94 14.52,19.94 14.22,19.64 14.22,19.07 14.07,18.92 13.61,18.92 13.48,19.05 13.48,19.94 13.97,20.42 13.97,21.21 13.48,21.69 13.48,26.52 14.17,27.2 14.17,28.17 13.18,29.16 13.18,32.99 13.72,33.53 14.68,33.53 16.28,35.13 18.45,35.13 18.79,34.79 18.79,33.65 19.27,33.17 20.51,33.17 20.75,32.93 20.75,31.49 21.22,31.02 21.22,30.73 v1(21.05,30.56)
TX0_DP_OUT: length 2.9
  TOP w0.13: J7.7 21.63,11.54 21.26,11.91 21.26,12.3 20.95,12.6 20.95,12.89 U13.A1
